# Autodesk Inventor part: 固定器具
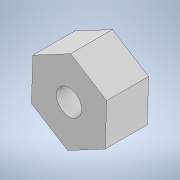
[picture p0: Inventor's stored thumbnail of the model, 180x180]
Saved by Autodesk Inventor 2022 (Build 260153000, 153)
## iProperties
Created: 2024-12
Part Number: 固定器具
Material: 一般
Document SubType Name: Modeling
Designer: jsat7
Density: 1 g/cm^3
Appearance: 既定
Author: jsat7
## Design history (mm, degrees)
sketch "スケッチ1"
  geometry: L1 (4.31, 3.482)-(-0.175, 1.094); L2 (-0.175, 1.094)-(-4.485, 3.785); L3 (-4.485, 3.785)-(-4.31, 8.862); L4 (-4.31, 8.862)-(0.175, 11.25); L5 (0.175, 11.25)-(4.485, 8.559); L6 (4.485, 8.559)-(4.31, 3.482); 2 further points
  constraints: 12 end point, 13 other
  dimensions: "d0" = 8.8 distance between parallel lines of L1 L4
extrude "押し出し1" new body sketch "スケッチ1" distance "d1" = 5; taper "d2" = 0 deg
sketch "スケッチ2"
  geometry: L1 (0.175, 11.25)-(-4.31, 8.862) reference; L2 (4.31, 3.482)-(4.485, 8.559) reference; C1 r 1.5 at (0, 6.172); 1 further point
  constraints: 1 centre point
  dimensions: "d3" = 4.4 distance from line of C1.centre L1; "d4" = 4.4 distance from line of L2 C1.centre; "d5" = 3 diameter of C1
extrude "押し出し2" cut sketch "スケッチ2" distance "d6" = 5; taper "d7" = 0 deg
node "ソリッド1"
